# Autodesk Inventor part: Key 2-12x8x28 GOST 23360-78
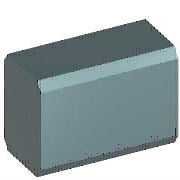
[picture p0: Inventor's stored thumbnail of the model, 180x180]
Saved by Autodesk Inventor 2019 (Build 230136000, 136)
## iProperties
Created: 2018-01
Part Number: Key 2-12x8x28 GOST 23360-78
Material: Steel, Mild
Description: Keyed joints with sunk keys
Document SubType Name: Modeling
Standard: GOST 23360-78 (2)
Designer: m.vorobev
Standards Organization: GOST
Language: en-US
Size Designation: 12 x 8 x 28
Categories: <MemberInstance><Categories><Category DisplayName="Shaft Parts" InternalName="7f7aeb1f-a693-4053-b835-cee3144e0d98" Mnemonic="SHFT"><Category DisplayName="Keys"
Density: 7.85 g/cm^3
Appearance: Semi-Polished
IsCustomPart: 1
Author: m.vorobev
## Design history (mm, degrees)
sketch "Sketch1"
  geometry: L1 (6, 6)-(26, 6); L2 (26, 6)-(26, -6); L3 (26, -6)-(6, -6); L4 (0, 8.4)-(0, -8.4) reference; L5 (-5.2, 0)-(31.2, 0) reference; L6 (6, 6)-(6, -6); A1 r 6 centre (6, 0) between (6, 6) and (6, -6)
  constraints: 8 end point, 3 tangent, 2 perpendicular, 2 point on circle, 1 centre point, 1 horizontal, 1 parallel, 1 point on line
  dimensions: "d0" = 6 radius of A1 (= 0.5 x PB); "d19" = 20 distance of L1.start L1.end
extrude "Body1" new body sketch "Sketch1" taper "d3" = 0 deg; stored distance "d4" = 10
body "Solid1"
workplane "Work Plane1"
workplane "Work Plane2"
chamfer "Chamfer1" distance "d8" = 0.4 (= PHH); stored, may be unused: second distance "d9" = 0.4 (= PHH), angle "d13" = 45 deg
other parameters: "d1" = -5 (= -PNT), "d2" = 3 (= PH - PNT), "NLG" = 28 [user parameter], "PB" = 12 [user parameter; used in 1 equation term], "PNT" = 5 [user parameter; used in 2 equation terms], "PH" = 8 [user parameter; used in 1 equation term], "PHH" = 0.4 [user parameter; used in 2 equation terms], "d10" = 0, "d16" = 0, "d17" = 0, "d18" = 0, "RR" = 0.25 [user parameter], "WDMIN" = 38 [user parameter], "WDMAX" = 44 [user parameter], "PLB1" = 34 [user parameter], "PUEB" = 3.3 [user parameter]
